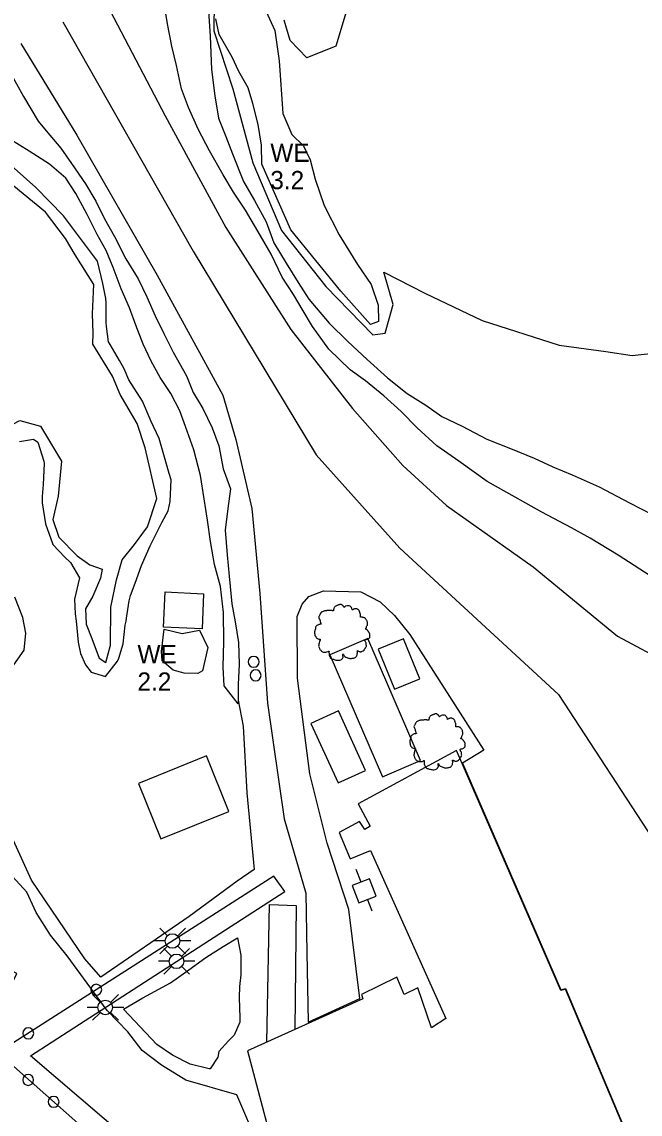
# Model space of a CAD drawing. Extents: x 2160437 to 2172832, y 205694 to 212444.
# Drawn here: x 2161197.1 to 2161366.8, y 210690.7 to 210990.4 of the extents above; entities that cross this region are included whole.
import ezdxf

# ---------------------------------------------------------------- set-up
doc = ezdxf.new("R2010")
doc.units = 0
for name, color, linetype in [('Default', 7, 'Continuous'), ('RD_EX_Bldg', 7, 'Continuous'), ('RD_EX_BldgApp', 7, 'Continuous'), ('RD_EX_Dam', 7, 'Continuous'), ('RD_EX_Driveway', 7, 'Continuous'), ('RD_EX_H2O', 7, 'Continuous'), ('RD_EX_H2O_Pond', 7, 'Continuous'), ('RD_EX_H2O_txCode', 7, 'Continuous'), ('RD_EX_LaneStripe', 7, 'Continuous'), ('RD_EX_Road_Post', 7, 'Continuous'), ('RD_EX_UT', 7, 'Continuous'), ('RD_EX_VEG', 7, 'Continuous'), ('RD_EX_VEG_ShrubLine', 7, 'Continuous'), ('RD_EX_VEG_TreeLine', 7, 'Continuous')]:
    doc.layers.add(name, color=color, linetype=linetype)

# ---------------------------------------------------------------- blocks, each defined once
blk = doc.blocks.new('POST')
at = {"layer": 'Default'}
for start, end in [(90, 270), (270, 90)]:
    blk.add_arc((0, 0), 0.0417, start, end, dxfattribs=at)
blk = doc.blocks.new('T2')
at = {"layer": 'RD_EX_VEG'}
for points in [[(0.05, 7.21), (-0.25, 7.24), (-0.57, 7.14), (-0.82, 7.04), (-1.05, 6.96), (-1.27, 6.86), (-1.57, 6.69), (-1.8, 6.49), (-1.92, 6.24), (-1.97, 6.01), (-2.02, 5.74), (-2.02, 5.56), (-2.15, 5.54), (-2.3, 5.56), (-2.55, 5.64), (-2.8, 5.64), (-3.05, 5.64), (-3.4, 5.61), (-3.75, 5.61), (-4.02, 5.56), (-4.35, 5.51), (-4.72, 5.39), (-5.07, 5.26), (-5.37, 5.01), (-5.62, 4.54), (-5.75, 4.19), (-5.9, 3.94), (-5.75, 3.49), (-5.57, 3.14), (-5.55, 2.94), (-5.47, 2.52), (-5.37, 2.29), (-5.25, 2.09), (-5.32, 2.07), (-5.7, 2.02), (-6, 1.92), (-6.42, 1.69), (-6.64, 1.47), (-6.74, 1.14), (-6.77, 0.79), (-6.87, 0.59), (-6.94, 0.32), (-6.97, 0.24), (-7.02, -0.08), (-6.92, -0.53), (-6.89, -0.88), (-6.77, -1.11), (-6.62, -1.28), (-6.44, -1.53), (-6.05, -1.76), (-5.72, -1.86), (-5.52, -1.88), (-5.7, -2.38), (-5.75, -2.73), (-5.87, -3.13), (-5.87, -3.21), (-5.92, -3.68), (-5.77, -4.01), (-5.7, -4.38), (-5.52, -4.61), (-5.25, -4.91), (-4.92, -5.13), (-4.42, -5.26), (-4.02, -5.23), (-3.45, -5.06), (-3.2, -4.98), (-3.22, -5.16), (-3.2, -5.53), (-3.2, -5.96), (-3.05, -6.28), (-2.95, -6.56), (-2.8, -6.81), (-2.47, -7.03), (-2.07, -7.11), (-1.65, -7.26), (-1.2, -7.33), (-0.7, -7.36), (-0.1, -7.21), (0.18, -7.08), (0.28, -6.91), (0.48, -6.53), (0.43, -6.31), (0.45, -5.71), (0.55, -5.88), (0.73, -6.23), (1.23, -6.53), (1.63, -6.71), (2.1, -6.86), (2.4, -6.93), (2.88, -6.86), (3.25, -6.78), (3.63, -6.66), (3.93, -6.38), (4.1, -6.11), (4.15, -5.83), (4.23, -5.46), (4.28, -5.28)], [(4.28, -5.28), (4.2, -5.11), (4.15, -4.86), (4.23, -4.88), (4.4, -4.93), (4.68, -5.06), (4.9, -5.13), (5.23, -5.11), (5.5, -5.01), (5.95, -4.73), (6.22, -4.26), (6.5, -3.86), (6.57, -3.53), (6.52, -3.31), (6.5, -2.81), (6.3, -2.56), (6.25, -2.43), (6.15, -2.03), (6.22, -1.98), (6.5, -1.93), (6.87, -1.81), (7.15, -1.68), (7.37, -1.51), (7.45, -1.28), (7.42, -0.88), (7.47, -0.48), (7.4, -0.33), (7.3, -0.18), (7.22, 0.02), (7.07, 0.17), (6.97, 0.32), (6.87, 0.42), (6.75, 0.57), (6.57, 0.69), (6.42, 0.74), (6.37, 0.89), (6.52, 1.09), (6.57, 1.19), (6.6, 1.42), (6.82, 1.77), (6.87, 2.17), (6.82, 2.59), (6.77, 2.87), (6.62, 3.14), (6.42, 3.39), (6.3, 3.56), (6.12, 3.69), (5.8, 3.81), (5.55, 3.86), (5.2, 3.86), (5, 3.91), (5.03, 3.96), (5.03, 4.11), (5.03, 4.39), (4.95, 4.84), (4.8, 5.34), (4.8, 5.36), (4.7, 5.61), (4.48, 5.81), (4.3, 5.91), (4.1, 6.04), (3.85, 6.06), (3.55, 6.06), (3.28, 6.01), (3.08, 5.91), (2.9, 5.79), (2.83, 5.94), (2.73, 6.24), (2.68, 6.39), (2.53, 6.56), (2.3, 6.76), (1.85, 6.89), (1.23, 6.81), (0.93, 6.61), (0.78, 6.44), (0.73, 6.56), (0.53, 6.76), (0.43, 6.94), (0.25, 7.06), (0.1, 7.16), (0, 7.21)]]:
    blk.add_spline(points, degree=3, dxfattribs=at)
blk = doc.blocks.new('PP')
at = {"layer": 'RD_EX_UT'}
for p, q in [((2.49, 2.51), (-2.51, 2.51)), ((-2.51, 2.51), (-2.51, -2.49)), ((2.49, -2.49), (2.49, 2.51)), ((-5.94, -0.05), (-2.47, -0.05)), ((-2.51, -2.49), (2.49, -2.49)), ((2.42, -0.05), (6.06, -0.05))]:
    blk.add_line(p, q, dxfattribs=at)

msp = doc.modelspace()

# ---------------------------------------------------------------- linework, layer by layer
at = {"layer": 'RD_EX_Bldg'}
for points in [[(2161281.65, 210816.75), (2161296.07, 210783.28), (2161306.46, 210787.76), (2161292.05, 210821.22)], [(2161294.87, 210818.25), (2161299.35, 210807.31), (2161306.27, 210810.14), (2161301.78, 210821.09)], [(2161276.42, 210797.93), (2161283.86, 210781.57), (2161291.44, 210785.01), (2161284, 210801.38)]]:
    msp.add_lwpolyline(points, close=True, dxfattribs=at)
msp.add_lwpolyline([(2161365.02, 210680.53), (2161346.27, 210724.99), (2161345.03, 210724.61), (2161316.41, 210790.5), (2161289.37, 210775.82), (2161292.66, 210769.75), (2161291.18, 210768.84), (2161289.71, 210771.01), (2161284.14, 210768), (2161287.15, 210760.74), (2161292.77, 210763.04), (2161313.4, 210716.9), (2161309.51, 210714.39), (2161305.79, 210725.37), (2161302.05, 210723.48), (2161299.99, 210728.24), (2161290.26, 210723.52), (2161290.66, 210722.33), (2161259.02, 210708.04), (2161269.17, 210669.72)], dxfattribs=at)
at = {"layer": 'RD_EX_BldgApp'}
msp.add_lwpolyline([(2161264.27, 210710.41), (2161265.09, 210748.19), (2161272.4, 210747.97), (2161272.02, 210713.91)], dxfattribs=at)
at = {"layer": 'RD_EX_Dam'}
for points in [[(2161236.38, 210833.97), (2161246.96, 210833.47), (2161246.52, 210823.86), (2161235.93, 210824.35)], [(2161247.79, 210788.98), (2161229.06, 210781.46), (2161235.19, 210766.2), (2161253.91, 210773.72)]]:
    msp.add_lwpolyline(points, close=True, dxfattribs=at)
for points in [[(2161266.22, 210756.03), (2161194.87, 210710.32), (2161191.13, 210712.33), (2161193.81, 210718.41), (2161190.92, 210719.65), (2161195.69, 210729.25), (2161173.37, 210740.08), (2161168.8, 210730.52), (2161107.55, 210760.18), (2161109.28, 210763.86), (2161101.33, 210767.83), (2161094.39, 210753.43), (2161160.45, 210720.78), (2161153.76, 210706.52), (2161182.3, 210693.89), (2161189.17, 210708.69), (2161223.64, 210678.3)], [(2161337.58, 210657.29), (2161328.75, 210653.17), (2161301.64, 210645.18), (2161296.84, 210644.02), (2161276.24, 210636.67), (2161253.83, 210660.23), (2161199.42, 210706.73), (2161235.09, 210729.77), (2161269.23, 210751.8), (2161266.22, 210756.03)]]:
    msp.add_lwpolyline(points, dxfattribs=at)
at = {"layer": 'RD_EX_Driveway'}
for points in [[(2161218.31, 210999.33), (2161236.44, 210964.63), (2161253.03, 210934.01), (2161270.92, 210906.01), (2161287.83, 210884.31), (2161301.65, 210868.71), (2161313.66, 210857.75), (2161337.45, 210840.85), (2161360.55, 210821.88), (2161374.92, 210814.19), (2161412.79, 210789.94)], [(2161196.83, 210984.5), (2161212.17, 210959.36), (2161234.25, 210920.87), (2161252.26, 210887.98), (2161255.81, 210875.82), (2161260.2, 210856.88), (2161262.38, 210833.59), (2161264.49, 210803.49), (2161269.11, 210771.69), (2161275.06, 210751.34), (2161275.32, 210735.08), (2161275.62, 210715.96), (2161289.82, 210722.41), (2161286.8, 210746.86), (2161280.88, 210765.05), (2161276.1, 210784.11), (2161272.73, 210810.32), (2161272.65, 210827.26), (2161273.98, 210830.62), (2161275.87, 210832.72), (2161279.83, 210834.26), (2161290.07, 210833.97), (2161295.38, 210831.26), (2161299.4, 210827.5), (2161303.54, 210822.35), (2161323.87, 210790.56), (2161318, 210786.98), (2161345.04, 210724.77), (2161346.33, 210725.13), (2161365.12, 210680.48)]]:
    msp.add_lwpolyline(points, dxfattribs=at)
at = {"layer": 'RD_EX_H2O'}
for points in [[(2161212.22, 210843.9), (2161215.7, 210841.45), (2161219.13, 210840.28), (2161218.63, 210837.8), (2161216.52, 210832.85), (2161214.56, 210829.33), (2161214.75, 210825.16), (2161216.24, 210821.23), (2161218.27, 210815.85), (2161220.09, 210814.59), (2161221.39, 210819.4), (2161221.51, 210829.84), (2161223.06, 210837.31), (2161224.61, 210842.83), (2161227.98, 210846.96), (2161231.58, 210851.87), (2161234.15, 210859.63), (2161230.88, 210873.54), (2161228.69, 210880.25), (2161224.02, 210888.14), (2161221.92, 210893.23), (2161216.53, 210902.01), (2161216.67, 210904.97), (2161216.48, 210910.26), (2161216.81, 210918.35), (2161211.67, 210926.45), (2161209.08, 210931.01), (2161203.57, 210938.24), (2161191.33, 210948.3)], [(2161183.71, 210882.87), (2161180.77, 210870.36), (2161181.73, 210867.5), (2161182.28, 210864.75), (2161187.51, 210871.07), (2161191.11, 210878.24), (2161196.55, 210881.05), (2161202.23, 210879.52), (2161208, 210869.9), (2161207.01, 210860.27), (2161205.6, 210853.85), (2161207.18, 210849.02), (2161212.22, 210843.9)], [(2161267.97, 210668.2), (2161256.09, 210696.02), (2161242.07, 210700.03), (2161235.37, 210704.12), (2161230.09, 210708.14), (2161226.17, 210713.24), (2161220.53, 210719.11), (2161209.53, 210734.13), (2161204.92, 210739.79), (2161200.96, 210746.04), (2161198.44, 210751.58), (2161192.46, 210758.11)]]:
    msp.add_lwpolyline(points, dxfattribs=at)
at = {"layer": 'RD_EX_H2O_Pond'}
msp.add_lwpolyline([(2161263.09, 210995.48), (2161266.51, 210988.03), (2161267.66, 210979.72), (2161268.74, 210965.28), (2161271.22, 210959.51), (2161274.42, 210956.44), (2161276.19, 210952.56), (2161277.55, 210947.23), (2161280.07, 210940), (2161284.18, 210931.99), (2161289.19, 210923.88), (2161292.97, 210918.34), (2161294.83, 210912.72), (2161294.99, 210908.19), (2161292.74, 210907.39), (2161284.61, 210916.52), (2161270.9, 210933.33), (2161262.96, 210951.37), (2161262.86, 210956.57), (2161261.91, 210962.27), (2161260.5, 210968.06), (2161259.18, 210972.36), (2161256.67, 210976.83), (2161254.78, 210980.7), (2161251.2, 210986.97), (2161250.36, 210991.24)], dxfattribs=at)
msp.add_lwpolyline([(2161235.37, 210817.68), (2161236.15, 210823.73), (2161241.04, 210822.59), (2161245.8, 210823.52), (2161248.11, 210818.77), (2161246.67, 210812.38), (2161245.37, 210811.59), (2161241.58, 210811.67), (2161238.62, 210812.5), (2161235.6, 210815.12)], close=True, dxfattribs=at)
at = {"layer": 'RD_EX_LaneStripe'}
msp.add_lwpolyline([(2161208.33, 210990.41), (2161244.14, 210927.49), (2161277.9, 210871.59), (2161300.83, 210845.97), (2161344.34, 210805.84), (2161401.86, 210717.85)], dxfattribs=at)
at = {"layer": 'RD_EX_UT'}
for p, q in [((2161234.94, 210741.74), (2161237.04, 210739.65)), ((2161239.85, 210739.58), (2161242.02, 210741.74)), ((2161236.41, 210738.21), (2161233.48, 210738.21)), ((2161243.48, 210738.21), (2161240.41, 210738.21)), ((2161234.94, 210734.67), (2161237.02, 210736.75)), ((2161236.05, 210736.16), (2161238.15, 210734.07)), ((2161239.87, 210736.82), (2161242.02, 210734.67)), ((2161240.96, 210734), (2161243.13, 210736.16)), ((2161237.52, 210732.63), (2161234.59, 210732.63)), ((2161244.59, 210732.63), (2161241.52, 210732.63)), ((2161236.05, 210729.09), (2161238.13, 210731.17)), ((2161240.98, 210731.24), (2161243.13, 210729.09)), ((2161216.49, 210723.52), (2161218.59, 210721.43)), ((2161221.4, 210721.36), (2161223.57, 210723.52)), ((2161217.96, 210719.99), (2161215.03, 210719.99)), ((2161216.49, 210716.45), (2161218.57, 210718.53)), ((2161221.42, 210718.6), (2161223.57, 210716.45)), ((2161225.03, 210719.99), (2161221.96, 210719.99))]:
    msp.add_line(p, q, dxfattribs=at)
for centre in [(2161238.41, 210738.19), (2161239.52, 210732.61), (2161219.96, 210719.97)]:
    msp.add_circle(centre, 2, dxfattribs=at)
at = {"layer": 'RD_EX_VEG_ShrubLine'}
for points in [[(2161249.84, 210996.14), (2161249.78, 210987.94), (2161254.98, 210972.02), (2161260.47, 210951.76), (2161268.33, 210933.13), (2161280.52, 210917.82), (2161293.37, 210904.54), (2161296.76, 210904.96), (2161298.96, 210912.89), (2161296.41, 210921.71), (2161307.68, 210915.93), (2161323.46, 210908.43), (2161344.54, 210901.67), (2161357.39, 210899.95), (2161364.61, 210898.83), (2161372.09, 210899.66), (2161378.45, 210905.96), (2161382.94, 210915.06), (2161390.65, 210923.64), (2161397.23, 210936.56), (2161399.86, 210949.89), (2161401.75, 210978), (2161401.64, 210987.79), (2161398.87, 211004.62)], [(2161286.64, 210994.98), (2161283.21, 210983.77), (2161275.29, 210980.56), (2161270.7, 210985.28), (2161269.04, 210990.93)], [(2161196.41, 210875.27), (2161200.28, 210875.91), (2161201.49, 210875.11), (2161203.14, 210869.85), (2161203.19, 210869.26), (2161202.9, 210863.48), (2161202.67, 210860.19), (2161202.62, 210858.4), (2161203.56, 210852.69), (2161203.56, 210852.69), (2161205.46, 210847.31), (2161205.58, 210847), (2161208.87, 210843.57), (2161210.39, 210842.07), (2161212.89, 210837.86), (2161212.89, 210837.86), (2161211.55, 210831.99), (2161211.69, 210827.97), (2161211.97, 210825.96), (2161212.53, 210820.24), (2161213.19, 210817.11), (2161214.5, 210814.01), (2161216.14, 210811.95), (2161220, 210810.77), (2161220, 210810.77), (2161223.3, 210815), (2161223.73, 210815.81), (2161224.88, 210819.76), (2161225.47, 210824.83), (2161225.66, 210825.94), (2161225.8, 210826.81), (2161226.54, 210831.51), (2161226.92, 210833.03), (2161228.19, 210836.42), (2161229.92, 210841.23), (2161229.92, 210841.23), (2161232.32, 210846.68), (2161233.49, 210848.98), (2161235.5, 210853.03), (2161237.2, 210856.23), (2161237.79, 210858.79), (2161238.02, 210864.72), (2161237.51, 210866.51), (2161236.2, 210871), (2161234.75, 210876.12), (2161232.48, 210880.98), (2161232.28, 210881.38), (2161230.17, 210886.29), (2161226.47, 210892.17), (2161225.15, 210895.22), (2161223.91, 210897.48), (2161221.3, 210901.86), (2161220.83, 210902.63), (2161220.33, 210906.82), (2161220.19, 210907.89), (2161220.2, 210913.35), (2161220.11, 210914.52), (2161219.3, 210918.59), (2161217.86, 210924.71), (2161208.52, 210937.22), (2161200.95, 210944.93), (2161194.15, 210951.02)], [(2161190.03, 210807.24), (2161197.67, 210818.05), (2161198.13, 210822.69), (2161197.37, 210826.99), (2161195.13, 210832.59)], [(2161256.43, 210804.3), (2161257.83, 210797.11), (2161258.81, 210778.82), (2161260.82, 210757.81), (2161256.13, 210754.65), (2161243.01, 210744.93), (2161218.78, 210728.29), (2161214.33, 210733.32), (2161199.71, 210754.93), (2161194.69, 210765.94)]]:
    msp.add_lwpolyline(points, dxfattribs=at)
msp.add_lwpolyline([(2161224.96, 210719.5), (2161230.27, 210722.57), (2161237.85, 210726.75), (2161242.87, 210730.3), (2161247.57, 210733.67), (2161252.31, 210736.65), (2161256.27, 210739.04), (2161257.22, 210734.31), (2161257.17, 210728.93), (2161256.84, 210725.69), (2161256.72, 210722.69), (2161256.94, 210717.13), (2161256.91, 210715.95), (2161255.37, 210712.34), (2161253.78, 210710.76), (2161251.15, 210707.86), (2161250.87, 210706.33), (2161248.77, 210703.16), (2161248.47, 210703.11), (2161243.28, 210704.41), (2161243.28, 210704.41), (2161238.38, 210706.85), (2161234.16, 210709.76), (2161234.16, 210709.76)], close=True, dxfattribs=at)
at = {"layer": 'RD_EX_VEG_TreeLine'}
for points in [[(2161369.53, 210838.45), (2161360.75, 210844.05), (2161353.08, 210848.77), (2161347.94, 210851.59), (2161339.83, 210855.89), (2161332.49, 210859.95), (2161324.78, 210864.31), (2161316.98, 210869.85), (2161310.96, 210874.07), (2161305.54, 210879.03), (2161301.16, 210883.52), (2161296.43, 210887.8), (2161291.39, 210891.96), (2161287.23, 210894.97), (2161281.36, 210900.63), (2161276.86, 210906.81), (2161274.28, 210911.12), (2161271.65, 210915.57), (2161268.54, 210920.37), (2161265.47, 210926.66), (2161262.44, 210931.92), (2161258.48, 210938.74), (2161255.21, 210943.73), (2161252.3, 210948.44), (2161248.61, 210955), (2161245.5, 210960.93), (2161242.81, 210966.93), (2161240.86, 210972.08), (2161239.48, 210978.48), (2161238.2, 210983.71), (2161237.08, 210989.87), (2161236.09, 210995.47)], [(2161248.22, 210994.77), (2161248.75, 210986.49), (2161249.16, 210977.38), (2161250.01, 210970.08), (2161251.02, 210963.97), (2161253.02, 210958.92), (2161254.9, 210954.18), (2161257.91, 210946.66), (2161260.94, 210941.4), (2161264.09, 210935.57), (2161266.27, 210929.82), (2161269.62, 210924.16), (2161272.9, 210918.9), (2161275.85, 210914.3), (2161281.44, 210907.76), (2161286.56, 210902.68), (2161291.88, 210897.77), (2161297.41, 210892.76), (2161302.86, 210888.41), (2161307.96, 210885.23), (2161312.34, 210882.12), (2161317.93, 210879.47), (2161324.73, 210875.9), (2161331.66, 210873.15), (2161337.7, 210870.67), (2161342.82, 210868.36), (2161348.09, 210866.11), (2161355.54, 210862.86), (2161363.87, 210858.48), (2161373.44, 210853.52)], [(2161193.68, 210976.93), (2161197.52, 210969.92), (2161201.58, 210963.16), (2161203.78, 210960.48), (2161207.79, 210955.77), (2161210.69, 210951.56), (2161214.56, 210945.93), (2161217.34, 210941.19), (2161219.8, 210936.38), (2161222.53, 210931.54), (2161225.58, 210925.36), (2161229.02, 210919.92), (2161231.34, 210914.93), (2161233.67, 210909.71), (2161236.02, 210904.94), (2161238.65, 210899.75), (2161242.23, 210893.32), (2161244.13, 210888.7), (2161246.71, 210884.29), (2161249.34, 210878.98), (2161251.12, 210874.07), (2161252.37, 210867.76), (2161254.33, 210862.24), (2161253.64, 210856.88), (2161252.9, 210850.9), (2161253.44, 210844.17), (2161253.98, 210838.31), (2161254.67, 210830.76), (2161255.61, 210825.81), (2161256.52, 210820.14), (2161256.72, 210814.19), (2161256.44, 210808.59), (2161256.43, 210803.32), (2161252.63, 210808.23), (2161252.29, 210813.36), (2161252.47, 210820.41), (2161252.4, 210828.31), (2161251.61, 210835.51), (2161249.98, 210841.51), (2161248.89, 210847.8), (2161248.07, 210853.67), (2161247.09, 210859.56), (2161246.09, 210865.92), (2161244.26, 210873), (2161242.46, 210878.1), (2161240.4, 210883.67), (2161237.93, 210888.44), (2161235, 210892.83), (2161232.61, 210897.27), (2161230.35, 210902), (2161228.36, 210907.19), (2161226.62, 210911.92), (2161224.36, 210917.17), (2161222.13, 210922.98), (2161220.2, 210927.68), (2161217.79, 210932.07), (2161215, 210937.56), (2161211.93, 210943.3), (2161209.1, 210947.53), (2161204.63, 210951.35), (2161199.06, 210954.92), (2161193.74, 210958.25)]]:
    msp.add_lwpolyline(points, dxfattribs=at)

# ---------------------------------------------------------------- block references
at = {"layer": 'RD_EX_Road_Post', "xscale": 36, "yscale": 36}
for p in [(2161260.7, 210814.8), (2161261.23, 210811.1), (2161217.48, 210724.81), (2161198.83, 210712.86), (2161198.81, 210700.09), (2161205.77, 210694.06)]:
    msp.add_blockref('POST', p, dxfattribs=at)
at = {"layer": 'RD_EX_UT', "xscale": 1.0199999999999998, "yscale": 1.02, "rotation": 111.005511}
msp.add_blockref('PP', (2161291.01, 210752), dxfattribs=at)
at = {"layer": 'RD_EX_VEG', "xscale": 1.0499999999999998, "yscale": 1.0499999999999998}
for p in [(2161284.75, 210822.97), (2161310.9, 210792.94)]:
    msp.add_blockref('T2', p, dxfattribs=at)

# ---------------------------------------------------------------- texts
at = {"layer": 'RD_EX_H2O_txCode'}
for s, p in [('WE', (2161265.27, 210952.01)), ('3.2', (2161265.27, 210944.51)), ('WE', (2161228.81, 210814.4)), ('2.2', (2161228.81, 210806.9))]:
    msp.add_text(s, height=5, dxfattribs=at).set_placement(p)

doc.saveas('drawing.dxf')
